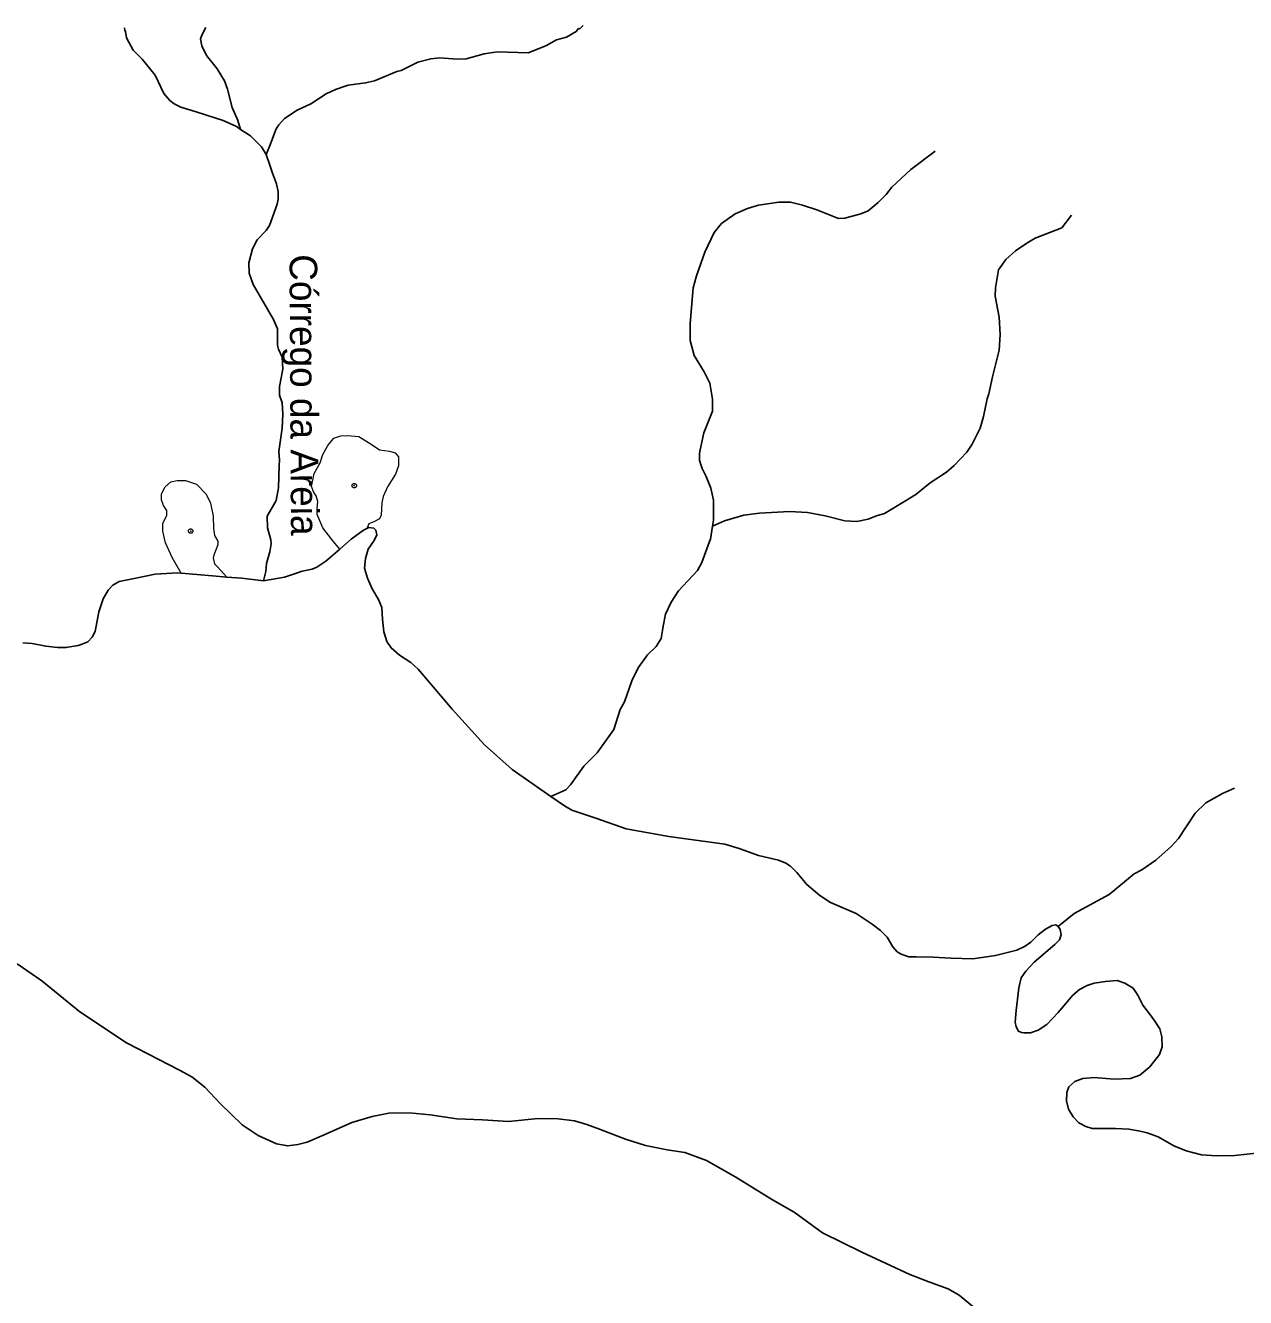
# Model space of a CAD drawing. Extents: x 396 to 422.2, y 7649.8 to 7677.6.
# Drawn here: x 407.27 to 411.685, y 7672.969 to 7677.575 of the extents above; entities that cross this region are included whole.
import ezdxf
from ezdxf.enums import TextEntityAlignment as Align

# ---------------------------------------------------------------- set-up
doc = ezdxf.new("R2010")
doc.units = 0
doc.header["$LTSCALE"] = 0.032
doc.header["$PDMODE"] = 32
doc.header["$PDSIZE"] = 0.016
doc.linetypes.add('SHORT_DASHED', pattern=[2.7, 1.5, -1.2])
for name, color, linetype, lineweight in [('2', 7, 'Continuous', 25), ('21', 7, 'SHORT_DASHED', 13), ('7', 7, 'Continuous', 25)]:
    doc.layers.add(name, color=color, linetype=linetype, lineweight=lineweight)
doc.layers.add('61', color=7, linetype='Continuous')

msp = doc.modelspace()

# ---------------------------------------------------------------- linework, layer by layer
at = {"layer": '2'}
for points in [[(408.5055, 7675.7535), (408.4927, 7675.7471), (408.4484, 7675.7156), (408.4069, 7675.6794)], [(409.1705, 7674.7836), (409.0305, 7674.8808), (408.9312, 7674.9703), (408.8142, 7675.0991), (408.6903, 7675.2446), (408.6638, 7675.2682), (408.6235, 7675.2948), (408.593, 7675.3213), (408.5772, 7675.3449), (408.5664, 7675.3793), (408.5615, 7675.4256), (408.5595, 7675.4678), (408.5477, 7675.4964), (408.5241, 7675.5347), (408.5074, 7675.574), (408.4966, 7675.6104), (408.4996, 7675.6448), (408.5104, 7675.6793), (408.532, 7675.7097), (408.5409, 7675.7304), (408.5379, 7675.7471), (408.53, 7675.755), (408.5123, 7675.7569), (408.5055, 7675.7535)], [(408.4069, 7675.6794), (408.357, 7675.636), (408.3235, 7675.6134), (408.3068, 7675.6065), (408.2705, 7675.5996), (408.2469, 7675.5908), (408.2065, 7675.577), (408.1309, 7675.5648)], [(407.8336, 7675.5916), (407.8211, 7675.5927), (407.7395, 7675.5878), (407.6628, 7675.5721), (407.6087, 7675.5613), (407.5861, 7675.5485), (407.5684, 7675.5308), (407.5507, 7675.4993), (407.5349, 7675.4521), (407.5212, 7675.3803), (407.5113, 7675.3597), (407.4956, 7675.3439), (407.4708, 7675.3343), (407.4602, 7675.3302), (407.416, 7675.3223), (407.3855, 7675.3233), (407.3432, 7675.3272), (407.294, 7675.3371), (407.2606, 7675.34)], [(407.9979, 7675.5781), (407.9469, 7675.5819), (407.8336, 7675.5916)], [(408.1309, 7675.5648), (408.0522, 7675.574), (407.9979, 7675.5781)], [(411.0069, 7674.3124), (410.9981, 7674.3184), (410.9853, 7674.3164), (410.9608, 7674.3036), (410.9342, 7674.282), (410.9077, 7674.2564), (410.888, 7674.2417), (410.8575, 7674.2269), (410.7798, 7674.2082), (410.6982, 7674.1955), (410.6186, 7674.1984), (410.5547, 7674.2014), (410.4947, 7674.2023), (410.4662, 7674.2033), (410.4386, 7674.2122), (410.4239, 7674.221), (410.4091, 7674.2387), (410.3885, 7674.2741), (410.3639, 7674.2987), (410.3334, 7674.3213), (410.2754, 7674.3597), (410.183, 7674.4), (410.1446, 7674.4246), (410.0974, 7674.4649), (410.061, 7674.5081), (410.0384, 7674.5308), (410.0217, 7674.5426), (409.9952, 7674.5524), (409.9224, 7674.5701), (409.8526, 7674.5957), (409.8005, 7674.6104), (409.5979, 7674.6389), (409.4435, 7674.6665), (409.3334, 7674.7048), (409.2469, 7674.7343), (409.2203, 7674.75), (409.1705, 7674.7836)], [(411.7356, 7673.4934), (411.6461, 7673.4835), (411.5802, 7673.4826), (411.5252, 7673.4865), (411.4701, 7673.5003), (411.4259, 7673.5189), (411.3688, 7673.5514), (411.3295, 7673.5652), (411.298, 7673.573), (411.2626, 7673.5789), (411.2144, 7673.5809), (411.1761, 7673.5809), (411.1299, 7673.5819), (411.1073, 7673.5888), (411.0817, 7673.6015), (411.061, 7673.6242), (411.0443, 7673.6517), (411.0374, 7673.6812), (411.0384, 7673.7117), (411.0453, 7673.7323), (411.0669, 7673.751), (411.0964, 7673.7628), (411.1377, 7673.7658), (411.2095, 7673.7599), (411.2685, 7673.7618), (411.302, 7673.7746), (411.3383, 7673.8051), (411.3737, 7673.8493), (411.3836, 7673.8769), (411.3816, 7673.9132), (411.3747, 7673.9418), (411.357, 7673.9703), (411.3374, 7673.9968), (411.3138, 7674.0283), (411.2951, 7674.0637), (411.2784, 7674.0893), (411.2479, 7674.1079), (411.2203, 7674.1168), (411.1781, 7674.1138), (411.1377, 7674.107), (411.1122, 7674.0991), (411.0846, 7674.0843), (411.0601, 7674.0637), (411.007, 7674.0017), (410.9657, 7673.9585), (410.9342, 7673.9378), (410.9067, 7673.928), (410.8831, 7673.928), (410.8742, 7673.929), (410.8634, 7673.9339), (410.8546, 7673.9496), (410.8516, 7673.9663), (410.8546, 7674.0086), (410.8644, 7674.0912), (410.8732, 7674.1266), (410.89, 7674.1512), (410.9204, 7674.1837), (410.9952, 7674.2476), (411.0119, 7674.2643), (411.0178, 7674.283), (411.0148, 7674.3017), (411.0069, 7674.3124)], [(410.7119, 7672.9265), (410.6487, 7672.9776), (410.6084, 7673.0005), (410.5385, 7673.026), (410.4699, 7673.0529), (410.2964, 7673.1336), (410.1539, 7673.2035), (410.0517, 7673.2788), (409.9737, 7673.3232), (409.8406, 7673.4052), (409.7344, 7673.4657), (409.6564, 7673.494), (409.5918, 7673.5047), (409.5138, 7673.5195), (409.4412, 7673.5424), (409.3471, 7673.5787), (409.3014, 7673.5962), (409.257, 7673.6096), (409.1978, 7673.6163), (409.1252, 7673.6177), (409.0176, 7673.6069), (408.9235, 7673.6123), (408.8307, 7673.6163), (408.7339, 7673.6311), (408.6586, 7673.6378), (408.5846, 7673.6365), (408.5241, 7673.6244), (408.4502, 7673.6029), (408.3507, 7673.5585), (408.2888, 7673.5316), (408.2552, 7673.5235), (408.2189, 7673.5182), (408.1785, 7673.5262), (408.1113, 7673.5558), (408.0535, 7673.5948), (407.9755, 7673.6701), (407.919, 7673.7306), (407.872, 7673.7683), (407.8276, 7673.7925), (407.6353, 7673.892), (407.4659, 7674.0036), (407.3287, 7674.1166), (407.24, 7674.1771)]]:
    msp.add_lwpolyline(points, dxfattribs=at)
at = {"layer": '21'}
for points in [[(408.4069, 7675.6794), (408.3786, 7675.7136), (408.3463, 7675.7562), (408.3258, 7675.8046), (408.3258, 7675.8267), (408.3272, 7675.8516), (408.3214, 7675.8722), (408.3126, 7675.8839), (408.3052, 7675.906), (408.314, 7675.953), (408.3361, 7675.9912), (408.3463, 7676.022), (408.364, 7676.0543), (408.386, 7676.0808), (408.411, 7676.0896), (408.4345, 7676.091), (408.4756, 7676.0866), (408.5211, 7676.0587), (408.5505, 7676.0382), (408.5872, 7676.0338), (408.6078, 7676.0279), (408.6195, 7676.0132), (408.6195, 7675.9809), (408.6092, 7675.95), (408.5799, 7675.9045), (408.5637, 7675.8693), (408.5593, 7675.8472), (408.5564, 7675.8017), (408.5505, 7675.7885), (408.5299, 7675.7782), (408.5123, 7675.7708), (408.5055, 7675.7535)], [(407.8336, 7675.5916), (407.7999, 7675.6489), (407.7764, 7675.7018), (407.7662, 7675.7444), (407.7662, 7675.7723), (407.7809, 7675.8017), (407.7809, 7675.8193), (407.7691, 7675.8369), (407.7618, 7675.8575), (407.7618, 7675.8795), (407.775, 7675.9045), (407.7955, 7675.9221), (407.819, 7675.928), (407.8484, 7675.928), (407.8881, 7675.9148), (407.9233, 7675.8781), (407.9395, 7675.8458), (407.9483, 7675.7988), (407.9498, 7675.7532), (407.9542, 7675.7283), (407.9659, 7675.7077), (407.9659, 7675.6945), (407.9571, 7675.6724), (407.9512, 7675.6577), (407.9483, 7675.646), (407.9542, 7675.6254), (407.9645, 7675.6152), (407.9979, 7675.5781)]]:
    msp.add_lwpolyline(points, dxfattribs=at)
for p in [(408.4594, 7675.9089), (407.8675, 7675.7444)]:
    msp.add_point(p, dxfattribs=at)
at = {"layer": '7'}
for points in [[(407.6279, 7677.566), (407.6287, 7677.5566), (407.6318, 7677.5531), (407.6347, 7677.5303), (407.6592, 7677.4857), (407.6923, 7677.4536), (407.7387, 7677.3952), (407.77, 7677.3292), (407.7916, 7677.3039), (407.8076, 7677.2913), (407.8315, 7677.2794), (407.8873, 7677.262), (407.985, 7677.2314), (408.0333, 7677.2096), (408.048, 7677.1988)], [(407.9226, 7677.5677), (407.9077, 7677.54), (407.9033, 7677.5267), (407.9079, 7677.5008), (407.925, 7677.466), (407.9593, 7677.4228), (407.9634, 7677.4177), (407.9898, 7677.3747), (408.0007, 7677.3444), (408.0178, 7677.2785), (408.038, 7677.2305), (408.048, 7677.1988)], [(409.2882, 7677.5751), (409.2758, 7677.563), (409.271, 7677.5638), (409.2625, 7677.5537), (409.2279, 7677.5322), (409.191, 7677.5231), (409.1522, 7677.5014), (409.0889, 7677.4759), (408.9772, 7677.4797), (408.9294, 7677.4727), (408.8645, 7677.4541), (408.8321, 7677.4526), (408.7695, 7677.4573), (408.7365, 7677.4548), (408.689, 7677.442), (408.629, 7677.412), (408.6132, 7677.408), (408.5327, 7677.3751), (408.5003, 7677.3671), (408.4377, 7677.3585), (408.4305, 7677.3561), (408.3917, 7677.3433), (408.3579, 7677.3275), (408.3025, 7677.291), (408.2532, 7677.268), (408.2076, 7677.238), (408.1859, 7677.2155), (408.177, 7677.2011), (408.1532, 7677.1365), (408.141, 7677.1077)], [(408.048, 7677.1988), (408.0835, 7677.1756), (408.1243, 7677.135), (408.141, 7677.1077)], [(408.141, 7677.1077), (408.1544, 7677.0693), (408.163, 7677.0407), (408.1775, 7677.002), (408.1837, 7676.9724), (408.1837, 7676.9465), (408.1805, 7676.9278), (408.1526, 7676.8513), (408.1407, 7676.8324), (408.1081, 7676.7989), (408.0907, 7676.7657), (408.0785, 7676.7159), (408.0794, 7676.6786), (408.0941, 7676.6367), (408.1675, 7676.5105), (408.1812, 7676.4768), (408.1822, 7676.4177), (408.1822, 7676.4171), (408.1855, 7676.4027), (408.1989, 7676.3743), (408.2012, 7676.3306), (408.1886, 7676.2678), (408.1886, 7676.2369), (408.1981, 7676.2084), (408.2014, 7676.1673), (408.1981, 7676.1168), (408.187, 7676.0321), (408.1885, 7676.0013), (408.1879, 7675.9822), (408.1853, 7675.9006), (408.1766, 7675.8548), (408.1438, 7675.7986), (408.1454, 7675.7562), (408.1574, 7675.7124), (408.1582, 7675.6977), (408.1543, 7675.6697), (408.1415, 7675.6267), (408.139, 7675.5976), (408.1309, 7675.5648)], [(410.562, 7677.1202), (410.4741, 7677.0538), (410.4053, 7676.989), (410.384, 7676.9629), (410.3551, 7676.934), (410.3188, 7676.9043), (410.2927, 7676.8928), (410.2353, 7676.8776), (410.2122, 7676.876), (410.1339, 7676.9077), (410.0815, 7676.9247), (410.038, 7676.935), (409.996, 7676.9358), (409.9226, 7676.9243), (409.8821, 7676.9123), (409.838, 7676.8929), (409.7889, 7676.8582), (409.7621, 7676.826), (409.728, 7676.7546), (409.6977, 7676.6686), (409.6857, 7676.6255), (409.675, 7676.4955), (409.6753, 7676.435), (409.6898, 7676.38), (409.7255, 7676.3214), (409.7463, 7676.2799), (409.7564, 7676.222), (409.7564, 7676.1786), (409.7247, 7676.1004), (409.7114, 7676.0384), (409.7085, 7676.025), (409.7086, 7675.9999), (409.718, 7675.9712), (409.7331, 7675.9424), (409.7499, 7675.8993), (409.7595, 7675.8567), (409.7596, 7675.7842), (409.7555, 7675.7624)], [(411.0554, 7676.8887), (411.0199, 7676.8419), (410.9235, 7676.8048), (410.8932, 7676.7874), (410.8521, 7676.7587), (410.8176, 7676.7274), (410.7915, 7676.6906), (410.7805, 7676.6251), (410.7789, 7676.5953), (410.793, 7676.5187), (410.7971, 7676.456), (410.793, 7676.3991), (410.7689, 7676.3028), (410.7566, 7676.2411), (410.7498, 7676.2231), (410.737, 7676.1593), (410.7245, 7676.1175), (410.6955, 7676.0594), (410.6764, 7676.0301), (410.631, 7675.9817), (410.6028, 7675.9573), (410.5435, 7675.9189), (410.492, 7675.8769), (410.4541, 7675.8537), (410.3787, 7675.8075), (410.3494, 7675.8), (410.319, 7675.7875), (410.2787, 7675.7795), (410.2353, 7675.7818), (410.1635, 7675.8001), (410.0996, 7675.8121), (410.0352, 7675.8153), (409.9263, 7675.8089), (409.8693, 7675.8017), (409.7992, 7675.7815), (409.7555, 7675.7624)], [(409.7555, 7675.7624), (409.7483, 7675.7152), (409.7452, 7675.7064), (409.7172, 7675.6308), (409.7016, 7675.6017), (409.6334, 7675.528), (409.6064, 7675.4875), (409.5857, 7675.4441), (409.5779, 7675.3997), (409.5752, 7675.3842), (409.5703, 7675.356), (409.5516, 7675.3259), (409.5209, 7675.2967), (409.4864, 7675.2491), (409.4644, 7675.2017), (409.4373, 7675.1267), (409.4221, 7675.098), (409.399, 7675.0265), (409.3382, 7674.9418), (409.2898, 7674.8934), (409.2426, 7674.8252), (409.2249, 7674.8079), (409.1705, 7674.7836)], [(411.6452, 7674.8138), (411.6018, 7674.7946), (411.5419, 7674.761), (411.5026, 7674.7225), (411.4429, 7674.6308), (411.4156, 7674.602), (411.3607, 7674.5534), (411.3102, 7674.5179), (411.2822, 7674.503), (411.1921, 7674.4288), (411.0646, 7674.36), (411.0137, 7674.3183), (411.0069, 7674.3124)]]:
    msp.add_lwpolyline(points, dxfattribs=at)

# ---------------------------------------------------------------- texts
at = {"layer": '61'}
msp.add_text('Córrego da Areia', height=0.1, rotation=270.293, dxfattribs=at).set_placement((408.2279, 7676.2373), align=Align.CENTER)

doc.saveas('drawing.dxf')
